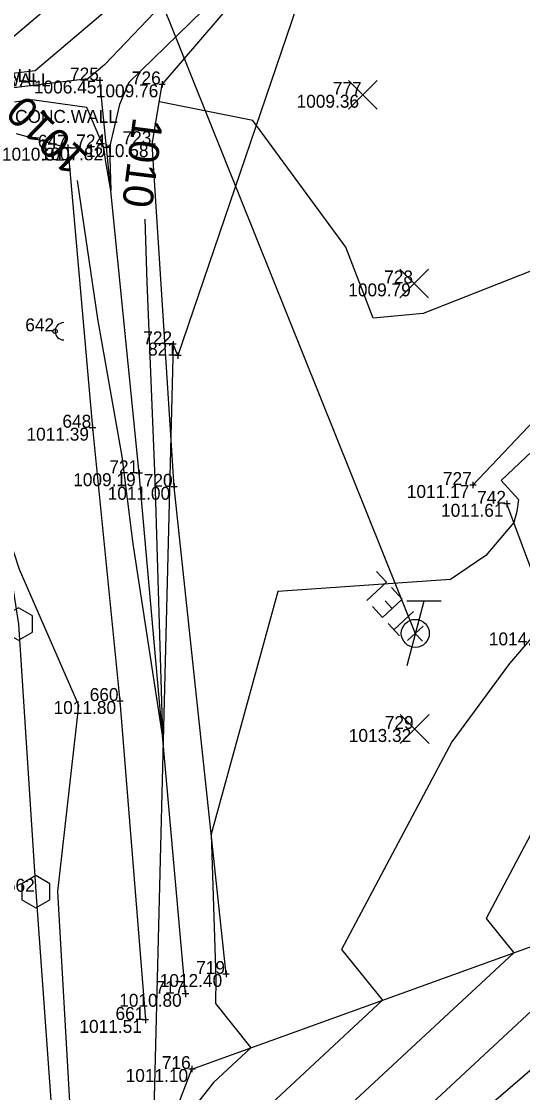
# Model space of a CAD drawing. Extents: x 2354693 to 2355622, y 637071 to 710080.
# Drawn here: x 2355383.9 to 2355430.4, y 709182.9 to 709282.3 of the extents above; entities that cross this region are included whole.
import ezdxf

# ---------------------------------------------------------------- set-up
doc = ezdxf.new("R2010")
doc.units = 0
for name, color, linetype in [('DR_X_Ditch', 7, 'Continuous'), ('DT_X_Contour_Major', 7, 'Continuous'), ('DT_X_Contour_Minor', 7, 'Continuous'), ('RD_X_Cells', 7, 'Continuous'), ('RD_X_GR_Lt', 7, 'Continuous'), ('SV_X_Break_Lines', 7, 'Continuous'), ('SV_X_Random_Point', 7, 'Continuous'), ('SV_X_Shot_Marker', 7, 'Continuous'), ('SV_X_Text_Comment', 7, 'Continuous'), ('SV_X_Text_Elevation', 7, 'Continuous'), ('SV_X_Text_Name', 7, 'Continuous'), ('SV_X_Toe_of_Slope', 7, 'Continuous'), ('SV_X_Top_of_Bank', 7, 'Continuous'), ('UT_X_Misc_Cells', 7, 'Continuous'), ('UT_X_Telecom', 7, 'Continuous'), ('VG_X_Tree_Line_Rt', 7, 'Continuous')]:
    doc.layers.add(name, color=color, linetype=linetype)

msp = doc.modelspace()

# ---------------------------------------------------------------- linework, layer by layer
at = {"layer": 'DR_X_Ditch'}
msp.add_lwpolyline([(2355399.11, 709192.107), (2355394.807, 709240.411), (2355391.782, 709270.647), (2355391.145, 709276.85)], dxfattribs=at)
at = {"layer": 'DT_X_Contour_Major'}
for points in [[(2355466.949, 709295.186), (2355452.845, 709268.07), (2355452.664, 709267.727), (2355452.573, 709267.618), (2355452.203, 709267.463), (2355421.162, 709255.221), (2355416.532, 709254.8), (2355413.992, 709261.4), (2355405.359, 709273.135), (2355396.684, 709274.875)], [(2355466.949, 709295.186), (2355452.845, 709268.07), (2355452.664, 709267.727), (2355452.573, 709267.618), (2355452.203, 709267.463), (2355421.162, 709255.221), (2355416.532, 709254.8), (2355413.992, 709261.4), (2355405.359, 709273.135), (2355396.684, 709274.875)], [(2355395.333, 709264.002), (2355395.51, 709258.147), (2355396.251, 709239.848), (2355396.973, 709216.099), (2355394.254, 709233.873), (2355393.211, 709241.966), (2355390.981, 709254.738), (2355389.082, 709267.561)], [(2355395.333, 709264.002), (2355395.51, 709258.147), (2355396.251, 709239.848), (2355396.973, 709216.099), (2355394.254, 709233.873), (2355393.211, 709241.966), (2355390.981, 709254.738), (2355389.082, 709267.561)], [(2355456.695, 709227.107), (2355457.481, 709226.197), (2355459.265, 709225.115), (2355454.221, 709205.335), (2355454.075, 709205.139), (2355453.898, 709204.805), (2355453.964, 709204.723), (2355452.925, 709203.757), (2355421.909, 709177.073), (2355419.268, 709170.597), (2355416.046, 709165.77), (2355412.705, 709160.358), (2355405.685, 709150.404), (2355404.68, 709148.792)], [(2355456.695, 709227.107), (2355457.481, 709226.197), (2355459.265, 709225.115), (2355454.221, 709205.335), (2355454.075, 709205.139), (2355453.898, 709204.805), (2355453.964, 709204.723), (2355452.925, 709203.757), (2355421.909, 709177.073), (2355419.268, 709170.597), (2355416.046, 709165.77), (2355412.705, 709160.358), (2355405.685, 709150.404), (2355404.68, 709148.792)]]:
    msp.add_lwpolyline(points, dxfattribs=at)
at = {"layer": 'DT_X_Contour_Minor'}
for points in [[(2355395.378, 709291.328), (2355380.244, 709278.504), (2355377.533, 709278.175), (2355377.476, 709277.579), (2355376.098, 709278.202), (2355375.927, 709278.258), (2355375.806, 709278.989), (2355375.543, 709278.66), (2355365.444, 709274.623), (2355364.182, 709273.928), (2355361.832, 709273.404), (2355347.575, 709268.496), (2355344.823, 709267.508), (2355344.134, 709267.763), (2355343.996, 709267.379), (2355341.88, 709263.698), (2355341.299, 709263.481), (2355330.832, 709262.519), (2355327.686, 709262.765), (2355325.646, 709262.822), (2355317.774, 709259.038)], [(2355395.378, 709291.328), (2355380.244, 709278.504), (2355377.533, 709278.175), (2355377.476, 709277.579), (2355376.098, 709278.202), (2355375.927, 709278.258), (2355375.806, 709278.989), (2355375.543, 709278.66), (2355365.444, 709274.623), (2355364.182, 709273.928), (2355361.832, 709273.404), (2355347.575, 709268.496), (2355344.823, 709267.508), (2355344.134, 709267.763), (2355343.996, 709267.379), (2355341.88, 709263.698), (2355341.299, 709263.481), (2355330.832, 709262.519), (2355327.686, 709262.765), (2355325.646, 709262.822), (2355317.774, 709259.038)], [(2355403.537, 709290.84), (2355391.576, 709278.322), (2355390.037, 709277.018), (2355381.334, 709275.961), (2355381.313, 709275.742), (2355376.465, 709277.932), (2355375.864, 709278.129), (2355375.79, 709278.574), (2355374.947, 709277.517), (2355369.041, 709275.156), (2355365.864, 709273.408), (2355359.948, 709272.086), (2355352.196, 709269.418), (2355345.743, 709267.101), (2355344.127, 709267.698), (2355343.804, 709266.798), (2355341.172, 709262.22), (2355340.042, 709259.574), (2355339.274, 709259.634), (2355334.287, 709259.774), (2355315.044, 709250.525)], [(2355403.537, 709290.84), (2355391.576, 709278.322), (2355390.037, 709277.018), (2355381.334, 709275.961), (2355381.313, 709275.742), (2355376.465, 709277.932), (2355375.864, 709278.129), (2355375.79, 709278.574), (2355374.947, 709277.517), (2355369.041, 709275.156), (2355365.864, 709273.408), (2355359.948, 709272.086), (2355352.196, 709269.418), (2355345.743, 709267.101), (2355344.127, 709267.698), (2355343.804, 709266.798), (2355341.172, 709262.22), (2355340.042, 709259.574), (2355339.274, 709259.634), (2355334.287, 709259.774), (2355315.044, 709250.525)], [(2355393.477, 709284.825), (2355385.14, 709277.761), (2355379.434, 709277.068), (2355379.395, 709276.661), (2355376.282, 709278.067), (2355375.896, 709278.193), (2355375.798, 709278.782), (2355375.245, 709278.088), (2355367.243, 709274.889), (2355365.023, 709273.668), (2355360.89, 709272.745), (2355349.886, 709268.957), (2355345.283, 709267.305), (2355344.131, 709267.73), (2355343.9, 709267.089), (2355340.361, 709260.932), (2355340.284, 709260.903), (2355338.897, 709260.776), (2355333.48, 709261.199), (2355329.967, 709261.298), (2355316.409, 709254.782)], [(2355393.477, 709284.825), (2355385.14, 709277.761), (2355379.434, 709277.068), (2355379.395, 709276.661), (2355376.282, 709278.067), (2355375.896, 709278.193), (2355375.798, 709278.782), (2355375.245, 709278.088), (2355367.243, 709274.889), (2355365.023, 709273.668), (2355360.89, 709272.745), (2355349.886, 709268.957), (2355345.283, 709267.305), (2355344.131, 709267.73), (2355343.9, 709267.089), (2355340.361, 709260.932), (2355340.284, 709260.903), (2355338.897, 709260.776), (2355333.48, 709261.199), (2355329.967, 709261.298), (2355316.409, 709254.782)], [(2355400.669, 709283.325), (2355393.85, 709276.684), (2355392.971, 709274.638), (2355392.061, 709270.667), (2355392.182, 709266.647), (2355391.715, 709269.321), (2355391.519, 709270.645), (2355389.957, 709274.349), (2355384.85, 709275.05), (2355383.235, 709274.854)], [(2355400.669, 709283.325), (2355393.85, 709276.684), (2355392.971, 709274.638), (2355392.061, 709270.667), (2355392.182, 709266.647), (2355391.715, 709269.321), (2355391.519, 709270.645), (2355389.957, 709274.349), (2355384.85, 709275.05), (2355383.235, 709274.854)], [(2355447.873, 709258.144), (2355428.413, 709239.732), (2355430.01, 709237.966), (2355429.853, 709236.861), (2355429.592, 709235.85), (2355426.984, 709232.779), (2355423.697, 709230.554), (2355407.685, 709229.45), (2355401.484, 709206.926), (2355401.928, 709193.482), (2355401.891, 709191.212), (2355405.185, 709187.105), (2355401.703, 709183.87), (2355400.314, 709182.112)], [(2355447.873, 709258.144), (2355428.413, 709239.732), (2355430.01, 709237.966), (2355429.853, 709236.861), (2355429.592, 709235.85), (2355426.984, 709232.779), (2355423.697, 709230.554), (2355407.685, 709229.45), (2355401.484, 709206.926), (2355401.928, 709193.482), (2355401.891, 709191.212), (2355405.185, 709187.105), (2355401.703, 709183.87), (2355400.314, 709182.112)], [(2355388.382, 709181.549), (2355387.248, 709201.609), (2355389.188, 709218.85), (2355383.697, 709231.486), (2355379.499, 709244.29), (2355376.776, 709247.498), (2355376.105, 709247.453), (2355373.371, 709254.729), (2355371.839, 709253.134), (2355371.28, 709251.764), (2355370.025, 709243.384), (2355369.092, 709233.774), (2355367.481, 709217.574), (2355362.053, 709192.157), (2355358.45, 709172.035)], [(2355388.382, 709181.549), (2355387.248, 709201.609), (2355389.188, 709218.85), (2355383.697, 709231.486), (2355379.499, 709244.29), (2355376.776, 709247.498), (2355376.105, 709247.453), (2355373.371, 709254.729), (2355371.839, 709253.134), (2355371.28, 709251.764), (2355370.025, 709243.384), (2355369.092, 709233.774), (2355367.481, 709217.574), (2355362.053, 709192.157), (2355358.45, 709172.035)], [(2355432.858, 709227.065), (2355429.195, 709222.752), (2355423.821, 709215.503), (2355413.597, 709196.226), (2355417.38, 709191.51), (2355406.148, 709181.073), (2355401.665, 709175.4), (2355399.283, 709169.521), (2355396.311, 709163.169), (2355393.277, 709154.483), (2355391.12, 709148.497), (2355389.298, 709141.689), (2355381.336, 709108.35), (2355380.044, 709103.586), (2355379.71, 709102.311), (2355378.563, 709101.105), (2355376.173, 709094.451), (2355359.352, 709054.558), (2355355.959, 709047.613), (2355331.07, 709003.59)], [(2355432.858, 709227.065), (2355429.195, 709222.752), (2355423.821, 709215.503), (2355413.597, 709196.226), (2355417.38, 709191.51), (2355406.148, 709181.073), (2355401.665, 709175.4), (2355399.283, 709169.521), (2355396.311, 709163.169), (2355393.277, 709154.483), (2355391.12, 709148.497), (2355389.298, 709141.689), (2355381.336, 709108.35), (2355380.044, 709103.586), (2355379.71, 709102.311), (2355378.563, 709101.105), (2355376.173, 709094.451), (2355359.352, 709054.558), (2355355.959, 709047.613), (2355331.07, 709003.59)], [(2355433.906, 709212.048), (2355427.03, 709199.086), (2355429.574, 709195.914), (2355410.593, 709178.275), (2355405.759, 709172.159), (2355404.343, 709170.038), (2355400.836, 709164.356), (2355398.858, 709160.131), (2355398.291, 709158.506), (2355394.496, 709147.971), (2355391.29, 709135.991), (2355385.606, 709112.193), (2355383.142, 709103.103), (2355382.503, 709100.671), (2355380.315, 709098.369), (2355375.754, 709085.672), (2355362.571, 709054.407), (2355353.881, 709036.624), (2355335.001, 709003.229)], [(2355433.906, 709212.048), (2355427.03, 709199.086), (2355429.574, 709195.914), (2355410.593, 709178.275), (2355405.759, 709172.159), (2355404.343, 709170.038), (2355400.836, 709164.356), (2355398.858, 709160.131), (2355398.291, 709158.506), (2355394.496, 709147.971), (2355391.29, 709135.991), (2355385.606, 709112.193), (2355383.142, 709103.103), (2355382.503, 709100.671), (2355380.315, 709098.369), (2355375.754, 709085.672), (2355362.571, 709054.407), (2355353.881, 709036.624), (2355335.001, 709003.229)], [(2355441.769, 709200.319), (2355421.104, 709181.115), (2355415.478, 709176.275), (2355414.999, 709175.1), (2355410.195, 709167.904), (2355405.213, 709159.835), (2355399.329, 709151.491), (2355397.872, 709147.446), (2355393.281, 709130.293), (2355389.876, 709116.036), (2355386.239, 709102.62), (2355385.296, 709099.03), (2355382.066, 709095.632), (2355375.335, 709076.894), (2355365.79, 709054.256), (2355351.803, 709025.634), (2355338.932, 709002.867)], [(2355441.769, 709200.319), (2355421.104, 709181.115), (2355415.478, 709176.275), (2355414.999, 709175.1), (2355410.195, 709167.904), (2355405.213, 709159.835), (2355399.329, 709151.491), (2355397.872, 709147.446), (2355393.281, 709130.293), (2355389.876, 709116.036), (2355386.239, 709102.62), (2355385.296, 709099.03), (2355382.066, 709095.632), (2355375.335, 709076.894), (2355365.79, 709054.256), (2355351.803, 709025.634), (2355338.932, 709002.867)]]:
    msp.add_lwpolyline(points, dxfattribs=at)
at = {"layer": 'RD_X_Cells'}
for points in [[(2355382.294, 709225.669), (2355383.592, 709224.919), (2355384.89, 709225.669), (2355384.89, 709227.169), (2355383.592, 709227.919), (2355382.294, 709227.169), (2355382.294, 709225.669)], [(2355383.9, 709200.826), (2355385.198, 709200.076), (2355386.496, 709200.826), (2355386.496, 709202.326), (2355385.198, 709203.076), (2355383.9, 709202.326), (2355383.9, 709200.826)]]:
    msp.add_lwpolyline(points, dxfattribs=at)
at = {"layer": 'RD_X_GR_Lt'}
msp.add_lwpolyline([(2355373.985, 709277.316), (2355381.031, 709242.7), (2355383.592, 709226.419), (2355385.198, 709201.576), (2355387.106, 709175.345)], dxfattribs=at)
at = {"layer": 'SV_X_Break_Lines'}
msp.add_lwpolyline([(2355425.791, 709239.319), (2355452.606, 709267.582), (2355470.645, 709304.294)], dxfattribs=at)
at = {"layer": 'SV_X_Random_Point'}
for p, q in [((2355414.235, 709274.193), (2355416.901, 709276.863)), ((2355414.235, 709276.863), (2355416.901, 709274.193)), ((2355419.012, 709256.691), (2355421.679, 709259.361)), ((2355419.012, 709259.361), (2355421.679, 709256.691)), ((2355419.049, 709215.346), (2355421.715, 709218.016)), ((2355419.049, 709218.016), (2355421.715, 709215.346))]:
    msp.add_line(p, q, dxfattribs=at)
at = {"layer": 'SV_X_Shot_Marker'}
for p, q in [((2355391.445, 709276.85), (2355390.845, 709276.85)), ((2355391.145, 709277.15), (2355391.145, 709276.55)), ((2355397.228, 709276.495), (2355396.628, 709276.495)), ((2355396.928, 709276.795), (2355396.928, 709276.195)), ((2355396.018, 709271.246), (2355396.018, 709270.646)), ((2355388.483, 709270.618), (2355387.883, 709270.618)), ((2355388.183, 709270.918), (2355388.183, 709270.318)), ((2355392.082, 709270.647), (2355391.482, 709270.647)), ((2355391.782, 709270.948), (2355391.782, 709270.347)), ((2355396.318, 709270.946), (2355395.718, 709270.946)), ((2355398.252, 709252.375), (2355397.652, 709252.375)), ((2355397.952, 709252.675), (2355397.952, 709252.075)), ((2355398.4, 709251.63), (2355398.4, 709251.03)), ((2355398.7, 709251.33), (2355398.1, 709251.33)), ((2355390.773, 709244.635), (2355390.173, 709244.635)), ((2355390.473, 709244.935), (2355390.473, 709244.335)), ((2355395.107, 709240.411), (2355394.507, 709240.411)), ((2355394.807, 709240.711), (2355394.807, 709240.111)), ((2355398.038, 709239.451), (2355398.038, 709238.851)), ((2355425.791, 709239.619), (2355425.791, 709239.019)), ((2355398.338, 709239.151), (2355397.738, 709239.151)), ((2355426.091, 709239.319), (2355425.491, 709239.319)), ((2355429.251, 709237.574), (2355428.651, 709237.574)), ((2355428.951, 709237.874), (2355428.951, 709237.274)), ((2355393.018, 709219.575), (2355393.018, 709218.975)), ((2355393.318, 709219.275), (2355392.718, 709219.275)), ((2355403.172, 709193.943), (2355402.572, 709193.943)), ((2355402.872, 709194.243), (2355402.872, 709193.643)), ((2355399.41, 709192.107), (2355398.81, 709192.107)), ((2355399.11, 709192.407), (2355399.11, 709191.807)), ((2355395.377, 709189.983), (2355395.377, 709189.383)), ((2355395.677, 709189.683), (2355395.077, 709189.683)), ((2355400.006, 709185.127), (2355399.406, 709185.127)), ((2355399.706, 709185.427), (2355399.706, 709184.827))]:
    msp.add_line(p, q, dxfattribs=at)
at = {"layer": 'SV_X_Toe_of_Slope'}
for points in [[(2355518.789, 709240.225), (2355469.969, 709224.898), (2355433.388, 709225.64), (2355428.951, 709237.574)], [(2355330.905, 709003.606), (2355357.29, 709054.655), (2355376.634, 709104.118), (2355386.677, 709149.188), (2355392.841, 709167.306), (2355399.706, 709185.127), (2355454.609, 709204.956), (2355491.093, 709216.855), (2355522.634, 709235.094)]]:
    msp.add_lwpolyline(points, dxfattribs=at)
at = {"layer": 'SV_X_Top_of_Bank'}
for points in [[(2355402.872, 709193.943), (2355398.038, 709239.151), (2355396.018, 709270.946), (2355396.928, 709276.495), (2355405.829, 709286.833), (2355411.149, 709299.506), (2355425.916, 709328.903), (2355430.112, 709344.026), (2355451.484, 709369.85), (2355463.891, 709385.714)], [(2355383.373, 709271.951), (2355388.183, 709270.618), (2355390.473, 709244.635), (2355393.018, 709219.275), (2355395.377, 709189.683)]]:
    msp.add_lwpolyline(points, dxfattribs=at)
at = {"layer": 'UT_X_Misc_Cells'}
msp.add_circle((2355386.998, 709253.584), 0.2, dxfattribs=at)
msp.add_arc((2355387.798, 709253.584), 0.8, 90, 270, dxfattribs=at)
at = {"layer": 'UT_X_Telecom'}
for p, q in [((2355345.904, 709410.895), (2355420.443, 709225.551)), ((2355421.247, 709228.551), (2355419.64, 709222.551)), ((2355422.847, 709228.551), (2355419.647, 709228.551)), ((2355421.175, 709226.233), (2355419.705, 709224.876)), ((2355420.44, 709225.555), (2355421.115, 709224.824))]:
    msp.add_line(p, q, dxfattribs=at)
for points in [[(2355415.93, 709228.61), (2355417.767, 709230.305), (2355416.846, 709231.303)], [(2355416.464, 709228.031), (2355417.385, 709227.033), (2355419.222, 709228.729), (2355418.234, 709229.799)], [(2355418.297, 709227.875), (2355417.642, 709228.583)], [(2355418.44, 709225.891), (2355420.277, 709227.587)], [(2355418.974, 709225.312), (2355417.919, 709226.455)]]:
    msp.add_lwpolyline(points, dxfattribs=at)
msp.add_circle((2355420.443, 709225.551), 1.3, dxfattribs=at)
at = {"layer": 'VG_X_Tree_Line_Rt'}
msp.add_lwpolyline([(2355430.113, 709344.442), (2355398.4, 709251.33), (2355397.952, 709252.375), (2355395.764, 709165.299), (2355393.835, 709147.98), (2355384.969, 709102.057), (2355364.4, 709052.049), (2355337.299, 709001.304)], dxfattribs=at)

# ---------------------------------------------------------------- texts
at = {"layer": 'DT_X_Contour_Major'}
for rotation, p in [(135.88043, (2355390.174, 709269.854)), (135.88043, (2355390.174, 709269.854)), (262.91688, (2355394.241, 709273.522)), (262.91688, (2355394.241, 709273.522))]:
    msp.add_text('1010', height=2.8, rotation=rotation, dxfattribs=at).set_placement(p)
at = {"layer": 'SV_X_Text_Comment'}
for p in [(2355375.766, 709276.73), (2355377.032, 709276.316), (2355383.278, 709272.925)]:
    msp.add_text('CONC.WALL', height=1.2, dxfattribs=at).set_placement(p)
at = {"layer": 'SV_X_Text_Elevation'}
for s, p in [('1006.45', (2355385.031, 709275.65)), ('1009.76', (2355390.778, 709275.295)), ('1009.36', (2355409.418, 709274.328)), ('1010.31', (2355382.062, 709269.418)), ('1007.82', (2355385.663, 709269.448)), ('1010.58', (2355389.871, 709269.746)), ('1009.79', (2355414.217, 709256.826)), ('1011.39', (2355384.344, 709243.435)), ('1009.19', (2355388.679, 709239.211)), ('1011.00', (2355391.879, 709237.951)), ('1011.17', (2355419.653, 709238.119)), ('1011.61', (2355422.829, 709236.374)), ('1014.32', (2355427.268, 709224.44)), ('1011.80', (2355386.86, 709218.075)), ('1013.32', (2355414.263, 709215.481)), ('1012.40', (2355396.713, 709192.743)), ('1010.80', (2355392.951, 709190.907)), ('1011.51', (2355389.255, 709188.483)), ('1011.10', (2355393.548, 709183.927))]:
    msp.add_text(s, height=1.2, dxfattribs=at).set_placement(p)
at = {"layer": 'SV_X_Text_Name'}
for s, p in [('725', (2355388.382, 709276.85)), ('726', (2355394.129, 709276.495)), ('777', (2355412.782, 709275.528)), ('647', (2355385.397, 709270.618)), ('724', (2355388.963, 709270.647)), ('723', (2355393.259, 709270.946)), ('728', (2355417.55, 709258.026)), ('642', (2355384.229, 709253.584)), ('722', (2355395.184, 709252.375)), ('821', (2355395.629, 709251.33)), ('648', (2355387.677, 709244.635)), ('721', (2355392.036, 709240.411)), ('727', (2355423.004, 709239.319)), ('720', (2355395.23, 709239.151)), ('742', (2355426.183, 709237.574)), ('660', (2355390.211, 709219.275)), ('729', (2355417.605, 709216.681)), ('662', (2355382.43, 709201.576)), ('719', (2355400.095, 709193.943)), ('717', (2355396.324, 709192.107)), ('661', (2355392.606, 709189.683)), ('716', (2355396.908, 709185.127))]:
    msp.add_text(s, height=1.2, dxfattribs=at).set_placement(p)

doc.saveas('drawing.dxf')
